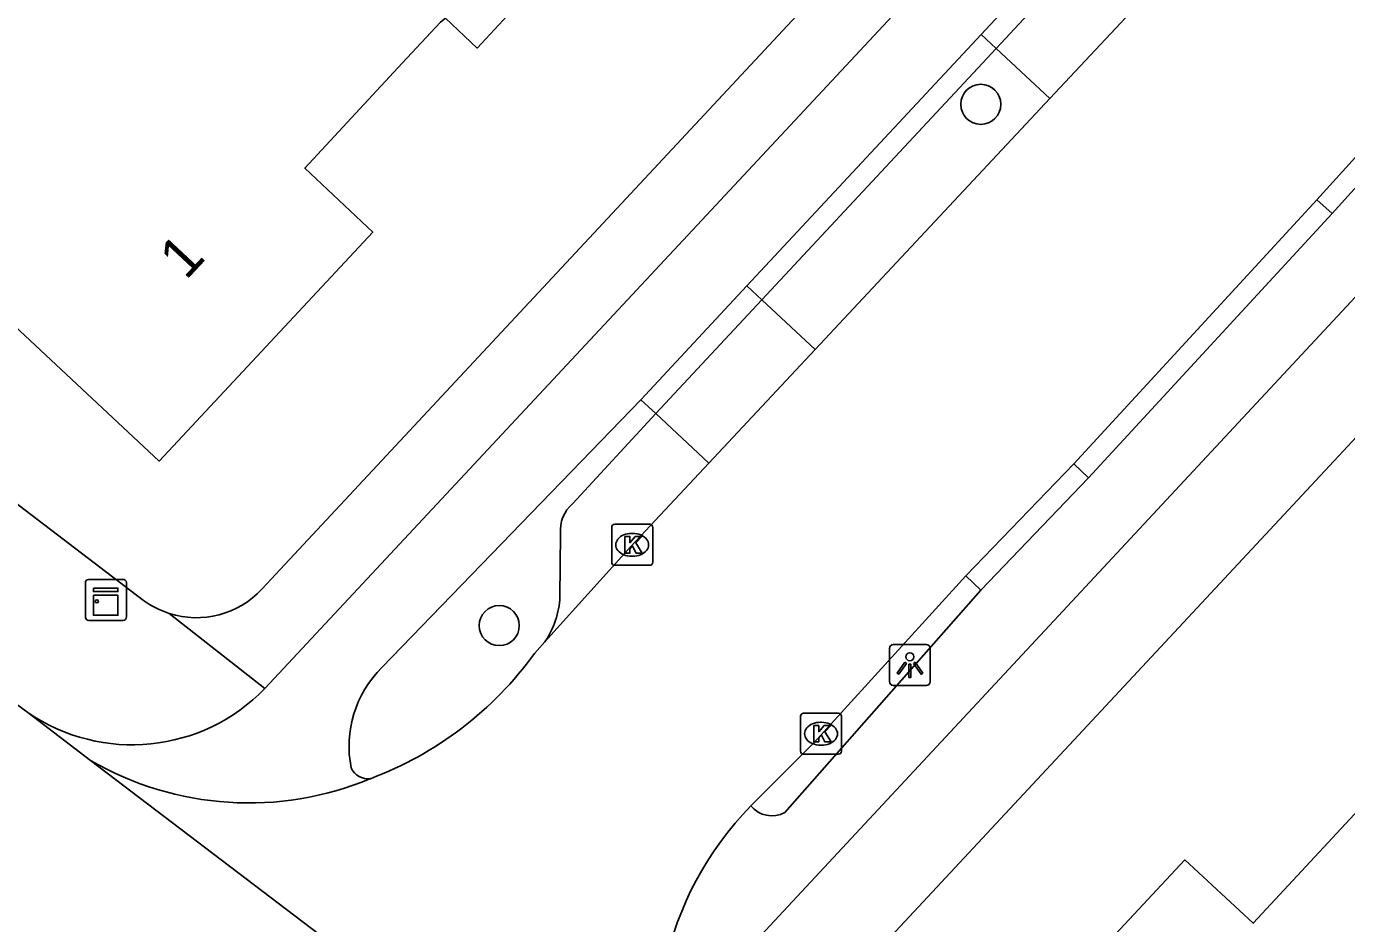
# Model space of a CAD drawing. Extents: x 159628 to 160723, y 388176 to 389416.
# Drawn here: x 160461.73 to 160493.96, y 388633.66 to 388655.56 of the extents above; entities that cross this region are included whole.
import ezdxf

# ---------------------------------------------------------------- set-up
doc = ezdxf.new("R2010")
doc.units = 0
for name, color, linetype in [('IMGEO_Boom', 7, 'Continuous'), ('IMGEO_Fietspad_gesloten', 7, 'Continuous'), ('IMGEO_Kast', 7, 'Continuous'), ('IMGEO_Kolk', 7, 'Continuous'), ('IMGEO_Lichtpunt', 7, 'Continuous'), ('IMGEO_Pand', 7, 'Continuous'), ('IMGEO_Pand_nummerreeks', 7, 'Continuous'), ('IMGEO_Parkeervlak_open', 7, 'Continuous'), ('IMGEO_Rijbaan_lokaal_gesloten', 7, 'Continuous'), ('IMGEO_Voetpad_open', 7, 'Continuous')]:
    doc.layers.add(name, color=color, linetype=linetype)

msp = doc.modelspace()

# ---------------------------------------------------------------- linework, layer by layer
at = {"layer": 'IMGEO_Boom'}
for centre in [(160485.026, 388653.654), (160473.271, 388640.932)]:
    msp.add_circle(centre, 0.489, dxfattribs=at)
at = {"layer": 'IMGEO_Fietspad_gesloten'}
for points in [[(160467.549, 388639.396), (160500, 388674.178), (160547.973, 388725.59)], [(160557.261, 388716.685), (160500, 388655.208), (160478.454, 388632.075)], [(160485.033, 388655.356), (160487.622, 388658.137)], [(160479.313, 388649.223), (160485.033, 388655.356)], [(160496.111, 388653.76), (160493.6, 388650.985)], [(160493.6, 388650.985), (160487.656, 388644.534)], [(160476.726, 388646.444), (160479.313, 388649.223)], [(160470.407, 388639.908), (160476.726, 388646.444)], [(160487.656, 388644.534), (160485.024, 388641.799)], [(160485.024, 388641.799), (160480.24, 388636.37)]]:
    msp.add_lwpolyline(points, dxfattribs=at)
for centre, radius, start, end in [((160472.297, 388637.989), 2.693, 134.563, 191.3269), ((160464.31, 388642.525), 4.503, 235.5283, 315.9948), ((160470.07, 388637.646), 0.454, 204.2393, 277.0104), ((160479.924, 388636.944), 0.655, 219.0661, 298.8227)]:
    msp.add_arc(centre, radius, start, end, dxfattribs=at)
at = {"layer": 'IMGEO_Kast'}
for p, q in [((160463.168, 388641.133), (160463.168, 388641.974)), ((160463.168, 388641.974), (160463.168, 388641.133)), ((160463.243, 388642.058), (160464.084, 388642.058)), ((160464.084, 388642.058), (160463.243, 388642.058)), ((160464.168, 388641.983), (160464.168, 388641.142)), ((160464.168, 388641.142), (160464.168, 388641.983)), ((160464.093, 388641.058), (160463.252, 388641.058)), ((160463.252, 388641.058), (160464.093, 388641.058))]:
    msp.add_line(p, q, dxfattribs=at)
for points in [[(160463.363, 388641.848), (160463.963, 388641.848), (160463.963, 388641.763), (160463.363, 388641.763), (160463.363, 388641.848)], [(160463.363, 388641.673), (160463.963, 388641.673), (160463.963, 388641.184), (160463.363, 388641.184), (160463.363, 388641.673)]]:
    msp.add_lwpolyline(points, dxfattribs=at)
msp.add_circle((160463.447, 388641.522), 0.0377, dxfattribs=at)
for centre, start, end in [((160464.09, 388641.98), 2.4484, 94.2845), ((160464.09, 388641.98), 2.4484, 94.2845), ((160463.246, 388641.98), 92.4484, 184.2845), ((160463.246, 388641.98), 92.4484, 184.2845), ((160463.246, 388641.136), 182.4484, 274.2845), ((160463.246, 388641.136), 182.4484, 274.2845), ((160464.09, 388641.136), 272.4484, 4.2845), ((160464.09, 388641.136), 272.4484, 4.2845)]:
    msp.add_arc(centre, 0.0779, start, end, dxfattribs=at)
at = {"layer": 'IMGEO_Kolk'}
for p, q in [((160476.091, 388643.403), (160476.943, 388643.403)), ((160476.016, 388642.477), (160476.016, 388643.329)), ((160476.504, 388643.183), (160476.529, 388643.183)), ((160477.017, 388643.329), (160477.017, 388642.477)), ((160476.943, 388642.403), (160476.091, 388642.403)), ((160476.527, 388642.623), (160476.502, 388642.623)), ((160480.626, 388637.866), (160480.626, 388638.718)), ((160480.701, 388638.792), (160481.553, 388638.792)), ((160481.114, 388638.572), (160481.139, 388638.572)), ((160481.627, 388638.718), (160481.627, 388637.866)), ((160481.137, 388638.012), (160481.112, 388638.012)), ((160481.553, 388637.792), (160480.701, 388637.792))]:
    msp.add_line(p, q, dxfattribs=at)
for points in [[(160476.091, 388643.403), (160476.943, 388643.403)], [(160476.016, 388642.477), (160476.016, 388643.329)], [(160476.337, 388643.103), (160476.46, 388643.103), (160476.46, 388642.952), (160476.59, 388643.103), (160476.754, 388643.103), (160476.608, 388642.952), (160476.761, 388642.703), (160476.609, 388642.703), (160476.524, 388642.867), (160476.46, 388642.8), (160476.46, 388642.703), (160476.337, 388642.703), (160476.337, 388643.103)], [(160477.017, 388643.329), (160477.017, 388642.477)], [(160476.943, 388642.403), (160476.091, 388642.403)], [(160480.626, 388637.866), (160480.626, 388638.718)], [(160480.701, 388638.792), (160481.553, 388638.792)], [(160481.627, 388638.718), (160481.627, 388637.866)], [(160480.947, 388638.492), (160481.07, 388638.492), (160481.07, 388638.341), (160481.2, 388638.492), (160481.364, 388638.492), (160481.218, 388638.341), (160481.371, 388638.092), (160481.219, 388638.092), (160481.134, 388638.256), (160481.07, 388638.189), (160481.07, 388638.092), (160480.947, 388638.092), (160480.947, 388638.492)], [(160481.553, 388637.792), (160480.701, 388637.792)]]:
    msp.add_lwpolyline(points, dxfattribs=at)
for centre, start, end in [((160476.093, 388643.327), 91.552, 178.448), ((160476.093, 388643.327), 91.552, 178.448), ((160476.941, 388643.327), 1.552, 88.448), ((160476.941, 388643.327), 1.552, 88.448), ((160476.093, 388642.479), 181.552, 268.448), ((160476.093, 388642.479), 181.552, 268.448), ((160476.941, 388642.479), 271.552, 358.448), ((160476.941, 388642.479), 271.552, 358.448), ((160480.703, 388638.716), 91.552, 178.448), ((160480.703, 388638.716), 91.552, 178.448), ((160481.551, 388638.716), 1.552, 88.448), ((160481.551, 388638.716), 1.552, 88.448), ((160480.703, 388637.868), 181.552, 268.448), ((160480.703, 388637.868), 181.552, 268.448), ((160481.551, 388637.868), 271.552, 358.448), ((160481.551, 388637.868), 271.552, 358.448)]:
    msp.add_arc(centre, 0.0765, start, end, dxfattribs=at)
for centre, major_axis, ratio, start_param, end_param in [((160476.503, 388642.903), (-0.387, 0.002), 0.722429, 4.712389, 7.853982), ((160476.528, 388642.903), (-0.39, 0.002), 0.717154, 1.570796, 4.712389), ((160481.113, 388638.292), (-0.387, 0.002), 0.722429, 4.712389, 7.853982), ((160481.138, 388638.292), (-0.39, 0.002), 0.717154, 1.570796, 4.712389)]:
    msp.add_ellipse(centre, major_axis=major_axis, ratio=ratio, start_param=start_param, end_param=end_param, dxfattribs=at)
at = {"layer": 'IMGEO_Lichtpunt'}
for p, q in [((160483.698, 388640.468), (160482.89, 388640.468)), ((160483.698, 388640.468), (160482.89, 388640.468)), ((160482.796, 388640.373), (160482.796, 388639.566)), ((160482.796, 388640.373), (160482.796, 388639.566)), ((160483.792, 388639.566), (160483.792, 388640.373)), ((160483.792, 388639.566), (160483.792, 388640.373)), ((160482.89, 388639.472), (160483.698, 388639.472)), ((160482.89, 388639.472), (160483.698, 388639.472))]:
    msp.add_line(p, q, dxfattribs=at)
for points in [[(160483.17, 388640.037), (160483.209, 388640.009), (160483.021, 388639.747), (160482.983, 388639.774), (160483.17, 388640.037)], [(160483.272, 388639.989), (160483.319, 388639.989), (160483.319, 388639.667), (160483.272, 388639.667), (160483.272, 388639.989)], [(160483.382, 388640.009), (160483.42, 388640.036), (160483.607, 388639.774), (160483.568, 388639.746), (160483.382, 388640.009)]]:
    msp.add_lwpolyline(points, dxfattribs=at)
msp.add_circle((160483.295, 388640.171), 0.0994, dxfattribs=at)
for centre, start, end in [((160482.89, 388640.373), 90, 180), ((160482.89, 388640.373), 90, 180), ((160483.698, 388640.373), 0, 90), ((160483.698, 388640.373), 0, 90), ((160482.89, 388639.566), 180, 270), ((160482.89, 388639.566), 180, 270), ((160483.698, 388639.566), 270, 0), ((160483.698, 388639.566), 270, 360)]:
    msp.add_arc(centre, 0.0946, start, end, dxfattribs=at)
at = {"layer": 'IMGEO_Pand'}
for points in [[(160479.594, 388665.714), (160479.483, 388665.594), (160478.629, 388664.669), (160476.197, 388662.035), (160477.812, 388660.496), (160472.734, 388655.028), (160471.955, 388655.754)], [(160471.955, 388655.754), (160471.835, 388655.659), (160470.903, 388654.657), (160468.521, 388652.097), (160470.181, 388650.532), (160464.967, 388644.948), (160461.313, 388648.361), (160455.028, 388654.227), (160460.023, 388659.588), (160459.203, 388660.352), (160462.612, 388664.011), (160462.835, 388664.25)], [(160504.214, 388628.844), (160503.997, 388628.611), (160500.588, 388624.952), (160500, 388625.5), (160499.754, 388625.729), (160494.759, 388620.367), (160494.682, 388620.439), (160492.774, 388618.395), (160489.119, 388621.807), (160491.012, 388623.835), (160488.444, 388626.213), (160484.789, 388629.625), (160490.007, 388635.212), (160491.678, 388633.665), (160495.001, 388637.25), (160495.089, 388637.345)]]:
    msp.add_lwpolyline(points, dxfattribs=at)
at = {"layer": 'IMGEO_Parkeervlak_open'}
for points in [[(160485.398, 388655.016), (160479.678, 388648.883)], [(160486.709, 388653.795), (160485.398, 388655.016)], [(160479.678, 388648.883), (160480.98, 388647.671)], [(160475.066, 388643.91), (160477.091, 388646.104)], [(160478.383, 388644.895), (160477.091, 388646.104)], [(160474.753, 388641.637), (160474.768, 388643.17)]]:
    msp.add_lwpolyline(points, dxfattribs=at)
for centre, radius, start, end in [((160475.615, 388643.259), 0.852, 130.1434, 185.987), ((160472.575, 388641.75), 2.181, 326.0903, 357.0398)]:
    msp.add_arc(centre, radius, start, end, dxfattribs=at)
at = {"layer": 'IMGEO_Rijbaan_lokaal_gesloten'}
for points in [[(160489.304, 388656.569), (160486.709, 388653.795)], [(160493.23, 388651.32), (160495.741, 388654.095)], [(160480.98, 388647.671), (160486.709, 388653.795)], [(160487.296, 388644.88), (160493.23, 388651.32)], [(160480.98, 388647.671), (160478.383, 388644.895)], [(160478.383, 388644.895), (160476.481, 388642.862), (160474.385, 388640.533)], [(160484.664, 388642.145), (160487.296, 388644.88)], [(160479.416, 388636.531), (160480.956, 388638.08), (160484.664, 388642.145)], [(160474.385, 388640.533), (160474.131, 388640.251)], [(160460.712, 388639.589), (160460.956, 388639.4), (160461.761, 388638.812)], [(160461.761, 388638.812), (160463.293, 388637.64)], [(160463.293, 388637.64), (160479.475, 388625.34)]]:
    msp.add_lwpolyline(points, dxfattribs=at)
for centre, radius, start, end in [((160467.061, 388645.368), 8.728, 290.5543, 324.1044), ((160467.158, 388644.321), 7.718, 239.952, 292.6114), ((160485.027, 388631), 7.879, 135.4146, 200.6343)]:
    msp.add_arc(centre, radius, start, end, dxfattribs=at)
at = {"layer": 'IMGEO_Voetpad_open'}
for points in [[(160467.475, 388641.82), (160500, 388676.697), (160547.944, 388728.109)], [(160480.943, 388631.314), (160500, 388651.764), (160560.212, 388716.376)], [(160487.987, 388657.797), (160485.398, 388655.016)], [(160485.398, 388655.016), (160485.033, 388655.356)], [(160448.24, 388654.005), (160450.027, 388652.645), (160464.587, 388641.545)], [(160493.6, 388650.985), (160493.23, 388651.32)], [(160479.313, 388649.223), (160479.678, 388648.883)], [(160479.678, 388648.883), (160477.091, 388646.104)], [(160477.091, 388646.104), (160476.726, 388646.444)], [(160487.296, 388644.88), (160487.656, 388644.534)], [(160485.024, 388641.799), (160484.664, 388642.145)], [(160465.214, 388641.227), (160467.549, 388639.396)]]:
    msp.add_lwpolyline(points, dxfattribs=at)
for centre, radius, start, end in [((160465.876, 388643.309), 2.185, 252.3528, 317.0395), ((160465.894, 388643.345), 2.224, 234.0144, 252.1994)]:
    msp.add_arc(centre, radius, start, end, dxfattribs=at)

# ---------------------------------------------------------------- texts
at = {"layer": 'IMGEO_Pand_nummerreeks'}
msp.add_text('1', height=1, rotation=46.9654, dxfattribs=at).set_placement((160465.621, 388649.342))

doc.saveas('drawing.dxf')
